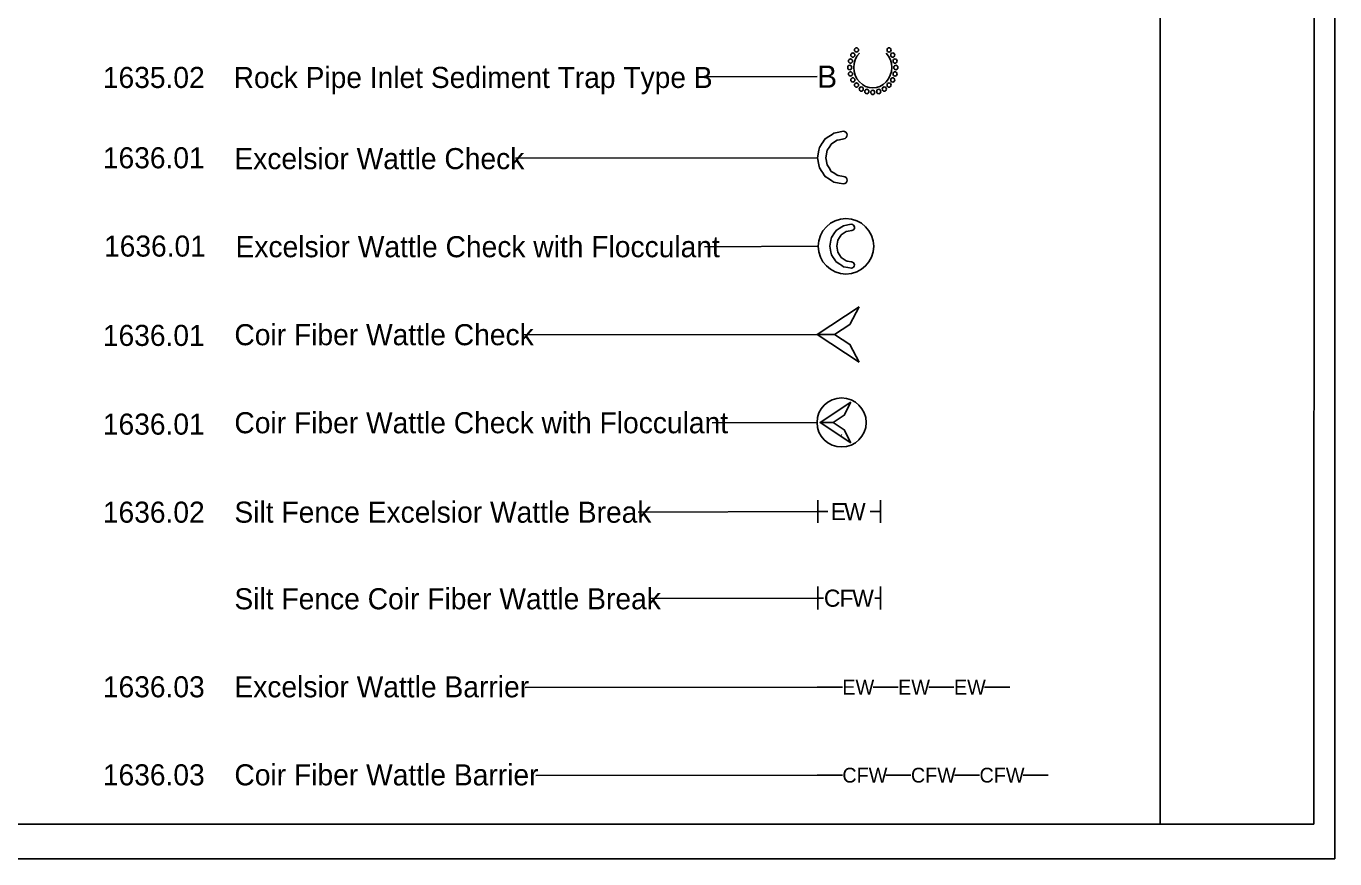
# Model space of a CAD drawing. Extents: x 1677124 to 1678808, y 1331209 to 1332299.
# Drawn here: x 1677966 to 1678808, y 1331209 to 1331745 of the extents above; entities that cross this region are included whole.
import ezdxf

# ---------------------------------------------------------------- set-up
doc = ezdxf.new("R2010")
doc.units = 0
for name, color, linetype in [('EC Title Sheet CELL', 7, 'Continuous'), ('Old_Level_61', 7, 'Continuous'), ('Sheet Plan CELL', 7, 'Continuous'), ('Sheet Plot Border Outside CELL', 7, 'Continuous'), ('z - Construction', 7, 'Continuous')]:
    doc.layers.add(name, color=color, linetype=linetype)

msp = doc.modelspace()

# ---------------------------------------------------------------- linework, layer by layer
at = {"layer": 'EC Title Sheet CELL'}
for p, q in [((1678397.95, 1331712.26), (1678474.68, 1331712.37)), ((1678485.83, 1331670.44), (1678483.6, 1331668.97)), ((1678487.52, 1331671.56), (1678485.83, 1331670.44)), ((1678488.95, 1331671.82), (1678487.52, 1331671.56)), ((1678491.77, 1331672.32), (1678488.95, 1331671.82)), ((1678481.13, 1331665), (1678480.28, 1331660.23)), ((1678481.13, 1331665), (1678482.28, 1331666.86)), ((1678483.37, 1331668.6), (1678482.28, 1331666.86)), ((1678483.37, 1331668.6), (1678483.6, 1331668.97)), ((1678280.67, 1331659.85), (1678474.81, 1331660.23)), ((1678480.28, 1331660.21), (1678480.28, 1331660.23)), ((1678480.28, 1331660.21), (1678481.07, 1331655.6)), ((1678481.07, 1331655.6), (1678482.23, 1331653.72)), ((1678482.23, 1331653.72), (1678483.64, 1331651.46)), ((1678483.64, 1331651.46), (1678485.23, 1331650.43)), ((1678485.23, 1331650.43), (1678487.52, 1331648.96)), ((1678488.12, 1331648.84), (1678487.52, 1331648.96)), ((1678488.12, 1331648.84), (1678491.49, 1331648.2)), ((1678489.88, 1331610.26), (1678490.07, 1331610.56)), ((1678491.93, 1331611.8), (1678490.07, 1331610.56)), ((1678493.34, 1331612.73), (1678491.93, 1331611.8)), ((1678494.54, 1331612.95), (1678493.34, 1331612.73)), ((1678496.89, 1331613.37), (1678494.54, 1331612.95)), ((1678402.05, 1331602.98), (1678475.29, 1331603.24)), ((1678488.01, 1331607.26), (1678487.3, 1331603.28)), ((1678487.3, 1331603.26), (1678487.3, 1331603.28)), ((1678487.3, 1331603.26), (1678487.96, 1331599.41)), ((1678488.01, 1331607.26), (1678488.97, 1331608.81)), ((1678489.88, 1331610.26), (1678488.97, 1331608.81)), ((1678487.96, 1331599.41), (1678488.93, 1331597.84)), ((1678488.93, 1331597.84), (1678490.11, 1331595.95)), ((1678490.11, 1331595.95), (1678491.43, 1331595.1)), ((1678491.43, 1331595.1), (1678493.34, 1331593.87)), ((1678493.85, 1331593.77), (1678493.34, 1331593.87)), ((1678493.85, 1331593.77), (1678496.65, 1331593.24)), ((1678499.51, 1331562.34), (1678499.51, 1331562.34)), ((1678286.14, 1331546.39), (1678474.55, 1331546.57)), ((1678494.81, 1331501.48), (1678494.81, 1331501.48)), ((1678407.13, 1331489.78), (1678474.55, 1331489.95)), ((1678490.44, 1331481.85), (1678490.04, 1331481.93)), ((1678474.95, 1331432.73), (1678474.95, 1331440.05)), ((1678515.3, 1331432.73), (1678515.3, 1331440.05)), ((1678359.39, 1331432.24), (1678474.95, 1331432.73)), ((1678474.95, 1331432.73), (1678481.54, 1331432.73)), ((1678474.95, 1331432.73), (1678474.95, 1331425.42)), ((1678508.72, 1331432.73), (1678515.3, 1331432.73)), ((1678515.3, 1331432.73), (1678515.3, 1331425.42)), ((1678474.95, 1331377.03), (1678474.95, 1331384.35)), ((1678515.34, 1331377.03), (1678515.34, 1331384.35)), ((1678366.36, 1331376.75), (1678474.95, 1331377.03)), ((1678474.95, 1331377.03), (1678478.62, 1331377.03)), ((1678474.95, 1331377.03), (1678474.95, 1331369.71)), ((1678511.68, 1331377.03), (1678515.34, 1331377.03)), ((1678515.34, 1331377.03), (1678515.34, 1331369.71)), ((1678286.85, 1331319.41), (1678474.68, 1331319.66)), ((1678293.64, 1331262.8), (1678474.68, 1331263.04))]:
    msp.add_line(p, q, dxfattribs=at)
for points in [[(1678491.49, 1331643.42), (1678488.66, 1331643.92), (1678485.36, 1331644.49), (1678484.07, 1331645.32), (1678482.5, 1331646.32), (1678479.72, 1331648.1), (1678479.67, 1331648.16), (1678479.23, 1331648.84), (1678479.15, 1331648.96), (1678478.19, 1331650.43), (1678477.52, 1331651.46), (1678476.05, 1331653.72), (1678475.68, 1331655.6), (1678474.81, 1331660.21), (1678474.81, 1331660.23), (1678475.72, 1331665), (1678476.08, 1331666.86), (1678477.23, 1331668.6), (1678477.47, 1331668.97), (1678478.45, 1331670.44), (1678479.19, 1331671.56), (1678479.37, 1331671.82), (1678479.74, 1331672.39), (1678479.75, 1331672.4), (1678482.09, 1331673.9), (1678484.16, 1331675.24), (1678485.42, 1331676.05), (1678488.59, 1331676.67), (1678491.39, 1331677.21)], [(1678496.65, 1331589.25), (1678494.3, 1331589.66), (1678491.55, 1331590.14), (1678490.46, 1331590.83), (1678489.15, 1331591.67), (1678486.83, 1331593.15), (1678486.8, 1331593.2), (1678486.43, 1331593.77), (1678486.36, 1331593.87), (1678485.56, 1331595.1), (1678485, 1331595.95), (1678483.77, 1331597.84), (1678483.47, 1331599.41), (1678482.74, 1331603.26), (1678482.74, 1331603.28), (1678483.5, 1331607.26), (1678483.79, 1331608.81), (1678484.75, 1331610.26), (1678484.95, 1331610.56), (1678485.77, 1331611.8), (1678486.39, 1331612.73), (1678486.54, 1331612.95), (1678486.85, 1331613.42), (1678486.86, 1331613.43), (1678488.81, 1331614.68), (1678490.54, 1331615.8), (1678491.59, 1331616.47), (1678494.24, 1331616.99), (1678496.57, 1331617.44)]]:
    msp.add_lwpolyline(points, dxfattribs=at)
for points in [[(1678501.58, 1331564.41), (1678474.55, 1331546.57), (1678485.86, 1331546.57), (1678495.71, 1331552.98)], [(1678501.58, 1331528.73), (1678474.55, 1331546.57), (1678485.86, 1331546.57), (1678495.71, 1331540.17)], [(1678496.33, 1331503), (1678476.51, 1331489.92), (1678484.8, 1331489.92), (1678492.03, 1331494.62)], [(1678496.33, 1331476.84), (1678476.51, 1331489.92), (1678484.8, 1331489.92), (1678492.03, 1331485.22)]]:
    msp.add_lwpolyline(points, close=True, dxfattribs=at)
msp.add_circle((1678490.34, 1331489.95), 15.79, dxfattribs=at)
for centre, radius, start, end in [((1678491.39, 1331674.75), 2.46, 278.88736, 90), ((1678491.49, 1331645.81), 2.39, 270, 90), ((1678493.14, 1331603.24), 17.85, 90, 270), ((1678493.14, 1331603.24), 17.85, 270, 90), ((1678496.57, 1331615.39), 2.05, 278.88736, 90), ((1678496.65, 1331591.24), 1.99, 270, 90)]:
    msp.add_arc(centre, radius, start, end, dxfattribs=at)
for centre, major_axis in [((1678499.91, 1331729.55), (0, -1.41)), ((1678520.87, 1331729.54), (0, 1.41)), ((1678496.07, 1331722.38), (0, -1.41)), ((1678497.55, 1331726.23), (0, -1.41)), ((1678523.23, 1331726.23), (0, 1.41)), ((1678524.71, 1331722.38), (0, 1.41)), ((1678495.56, 1331718.24), (0, -1.41)), ((1678496.07, 1331714.1), (0, -1.41)), ((1678497.55, 1331710.25), (0, -1.41)), ((1678523.23, 1331710.24), (0, 1.41)), ((1678524.71, 1331714.1), (0, 1.41)), ((1678525.22, 1331718.24), (0, 1.41)), ((1678499.9, 1331706.93), (0, -1.41)), ((1678502.97, 1331704.39), (0, -1.41)), ((1678506.55, 1331702.8), (0, -1.41)), ((1678510.39, 1331702.25), (0, -1.41)), ((1678514.23, 1331702.8), (0, -1.41)), ((1678517.8, 1331704.39), (0, -1.41)), ((1678520.87, 1331706.93), (0, 1.41))]:
    msp.add_ellipse(centre, major_axis=major_axis, ratio=0.927398, dxfattribs=at)
msp.add_ellipse((1678510.39, 1331718.24), major_axis=(0, 13.13), ratio=0.927398, start_param=0.785389, end_param=5.497624, dxfattribs=at)
at = {"layer": 'Old_Level_61'}
for p, q in [((1678474.68, 1331319.66), (1678490.81, 1331319.68)), ((1678510.56, 1331319.68), (1678526.69, 1331319.7)), ((1678546.45, 1331319.7), (1678562.58, 1331319.72)), ((1678582.33, 1331319.72), (1678598.46, 1331319.74)), ((1678474.68, 1331263.04), (1678490.81, 1331263.06)), ((1678518.79, 1331263.06), (1678534.92, 1331263.08)), ((1678562.9, 1331263.08), (1678579.03, 1331263.1)), ((1678607.01, 1331263.1), (1678623.14, 1331263.12))]:
    msp.add_line(p, q, dxfattribs=at)
at = {"layer": 'Sheet Plan CELL'}
for p, q in [((1678695.15, 1331231.56), (1678695.17, 1332276.27)), ((1678794.17, 1331231.56), (1678794.2, 1332276.27)), ((1677160.23, 1331231.56), (1678794.17, 1331231.56))]:
    msp.add_line(p, q, dxfattribs=at)
at = {"layer": 'Sheet Plot Border Outside CELL'}
msp.add_lwpolyline([(1677124.14, 1332298.56), (1678807.57, 1332298.56), (1678807.57, 1331209.28), (1677124.14, 1331209.28)], close=True, dxfattribs=at)
at = {"layer": 'z - Construction'}
msp.add_line((1677124.14, 1331209.28), (1678807.57, 1331209.28), dxfattribs=at)

# ---------------------------------------------------------------- texts
at = {"layer": 'EC Title Sheet CELL'}
for s, height, p in [('1635.02', 13.548, (1678015.18, 1331705.07)), ('Rock Pipe Inlet Sediment Trap Type B', 13.5461, (1678099.28, 1331705.07)), ('B', 14.29, (1678474.68, 1331705.22)), ('1636.01', 13.548, (1678015.18, 1331653.4)), ('Excelsior Wattle Check', 13.5651, (1678099.78, 1331652.85)), ('1636.01', 13.548, (1678015.93, 1331596.61)), ('Excelsior Wattle Check with Flocculant', 13.5651, (1678100.52, 1331596.2)), ('1636.01', 13.548, (1678015.18, 1331539.17)), ('Coir Fiber Wattle Check', 13.5651, (1678099.78, 1331539.61)), ('1636.01', 13.548, (1678015.18, 1331482.1)), ('Coir Fiber Wattle Check with Flocculant', 13.5651, (1678099.78, 1331482.99)), ('1636.02', 13.548, (1678015.18, 1331425.48)), ('Silt Fence Excelsior Wattle Break', 13.5705, (1678099.78, 1331425.46)), ('E', 11.02, (1678483.35, 1331427.11)), ('W', 11.02, (1678491.88, 1331427.09)), ('Silt Fence Coir Fiber Wattle Break', 13.5705, (1678099.78, 1331369.76)), ('C', 11.03, (1678478.94, 1331371.41)), ('F', 11.03, (1678488.99, 1331371.41)), ('W', 11.03, (1678497.15, 1331371.39)), ('1636.03', 13.548, (1678015.18, 1331313.16)), ('Excelsior Wattle Barrier', 13.5705, (1678099.78, 1331313.14)), ('EW', 9.51, (1678490.81, 1331314.92)), ('EW', 9.51, (1678526.69, 1331314.94)), ('EW', 9.51, (1678562.58, 1331314.96)), ('1636.03', 13.548, (1678015.18, 1331256.54)), ('Coir Fiber Wattle Barrier', 13.5705, (1678099.78, 1331256.52)), ('CFW', 9.51, (1678490.81, 1331258.3)), ('CFW', 9.51, (1678534.92, 1331258.33)), ('CFW', 9.51, (1678579.03, 1331258.35))]:
    msp.add_text(s, height=height, dxfattribs=at).set_placement(p)

doc.saveas('drawing.dxf')
